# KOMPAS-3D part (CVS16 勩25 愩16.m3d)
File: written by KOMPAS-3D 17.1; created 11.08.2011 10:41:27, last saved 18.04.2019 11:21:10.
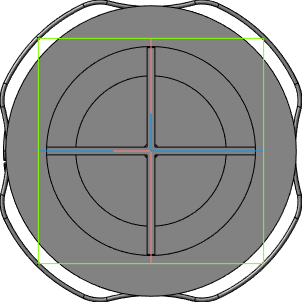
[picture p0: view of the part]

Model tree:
1. Плоскость XY
2. Плоскость ZX
3. Плоскость ZY
4. Ось X
5. Ось Y
6. Ось Z
7. Начало координат
8. Операция без истории:2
